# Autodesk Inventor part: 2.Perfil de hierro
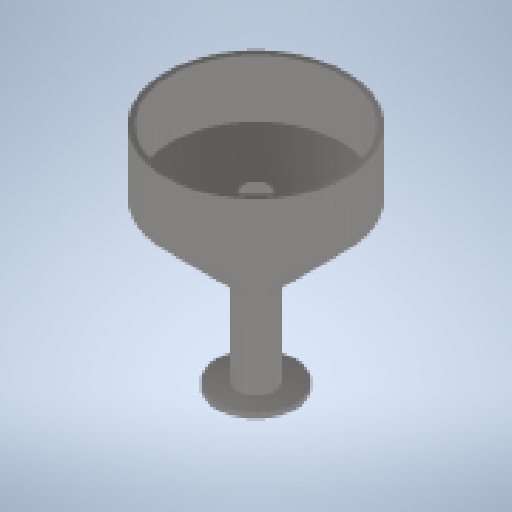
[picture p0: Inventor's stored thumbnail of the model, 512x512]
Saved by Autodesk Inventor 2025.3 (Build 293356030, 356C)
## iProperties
Created: 2025-10
Part Number: 2.Perfil de hierro
Material: Acero
Document SubType Name: Modeling
Designer: User
Density: 7.85 g/cm^3
Appearance: Pulido - Pequeña pirámide Moleteado
Author: User
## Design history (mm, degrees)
sketch "Boceto1"
  geometry: L1 (-17, -90)-(-17, 60); L2 (-17, 60)-(-86, 60); L3 (-86, 60)-(-86, 120); L4 (-17, -90)-(-37, -90); L5 (-81, 120)-(-81, 65); L6 (-81, 65)-(-12, 65); L7 (-12, 65)-(-12, -95); L8 (-12, -95)-(-37, -95); L9 (-86, 120)-(-81, 120); L10 (-37, -95)-(-37, -90); L11 (0, -138)-(0, 163) reference; L12 (-86, 60)-(-17, -9); 1 further point
  constraints: 22 end point, 5 perpendicular, 2 horizontal, 1 point on line, 1 vertical, 3 other
  dimensions: "d0" = 17 distance from line of point (0, 0) L1; "d1" = 150 distance of L1.start L1.end; "d2" = 69 distance of L1.end L2.end; "d3" = 20 distance of L1.start L4.end; "d4" = 90 distance from line of point (0, 0) L4; "d5" = 60 distance of L2.end L3.end; "d6" = 5 distance between parallel lines of L2 L6; "d9" = 45 deg angle of L1 L12
revolve "Revolución1" sketch "Boceto1" stored, may be unused: angle "d7" = 360 deg
node "Sólido1"
node "Acabados"
node "Finish1" dims "Finish1_Area" = 14389.0648
